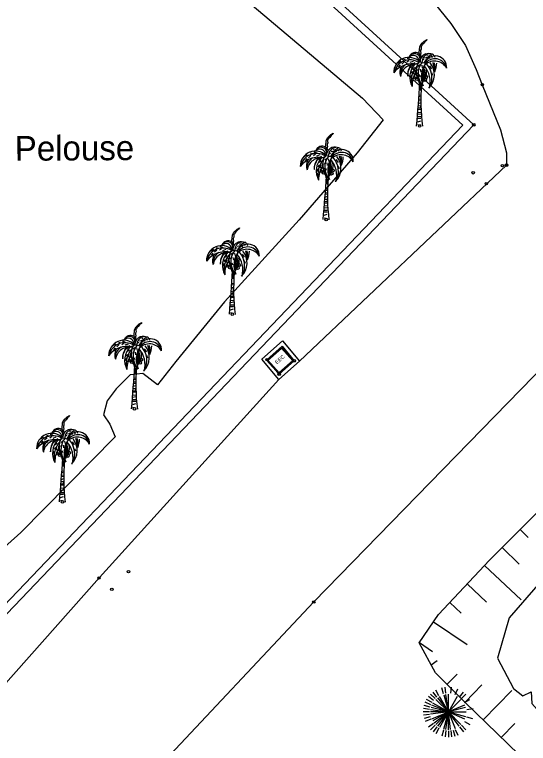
# Model space of a CAD drawing. Extents: x 344013 to 344423, y 298505 to 298795.
# Drawn here: x 344132.25 to 344152.54, y 298641.08 to 298669.85 of the extents above; entities that cross this region are included whole.
import ezdxf

# ---------------------------------------------------------------- set-up
doc = ezdxf.new("R2010")
doc.units = 0
for name, color, linetype in [('Default', 7, 'Continuous'), ('PS_BOLT', 7, 'Continuous'), ('PS_CONST', 7, 'Continuous'), ('RES_ELECTRICITE', 7, 'Continuous'), ('TOPO_POINT', 7, 'Continuous'), ('TOPO_TALUS-TERRAIN NATUREL', 7, 'Continuous'), ('VOIRIE_BORDURE', 7, 'Continuous'), ('VOIRIE_ESPACE VERT', 7, 'Continuous')]:
    doc.layers.add(name, color=color, linetype=linetype)

# ---------------------------------------------------------------- blocks, each defined once
blk = doc.blocks.new('RES_ELECTRICITE')
at = {"layer": 'RES_ELECTRICITE'}
for points in [[(0, 0), (0, 1), (1, 1), (1, 0)], [(0.05, 0.05), (0.05, 0.95), (0.95, 0.95), (0.95, 0.05)]]:
    blk.add_lwpolyline(points, close=True, dxfattribs=at)
blk.add_text('EEC', height=0.2, dxfattribs=at).set_placement((0.237, 0.46))
blk = doc.blocks.new('POINT_DISPLAY')
at = {"layer": 'Default'}
blk.add_circle((0, 0), 0.05, dxfattribs=at)
blk = doc.blocks.new('COCO')
at = {"layer": 'Default'}
for p, q in [((0.058, 1.14), (-0.03, 1.162)), ((-0.026, 1.226), (0.061, 1.212)), ((-0.046, 0.891), (0.052, 0.927)), ((0.054, 0.998), (-0.041, 0.985)), ((-0.037, 1.06), (0.056, 1.071)), ((0.047, 0.655), (-0.058, 0.642)), ((0.045, 0.292), (-0.07, 0.288)), ((-0.068, 0.371), (0.045, 0.374)), ((0.045, 0.47), (-0.065, 0.453)), ((-0.062, 0.537), (0.046, 0.552)), ((0.046, 0.033), (-0.076, 0.051)), ((-0.073, 0.17), (0.045, 0.209))]:
    blk.add_line(p, q, dxfattribs=at)
for points in [[(0.029, 2.551), (-0.016, 2.896), (0.002, 3.125), (0.059, 3.241), (0.173, 3.348), (0.189, 3.356), (0.282, 3.415), (0.266, 3.373), (0.2, 3.318), (0.143, 3.247), (0.093, 3.2), (0.081, 3.165), (0.057, 3.133), (0.057, 3.099), (0.06, 3.037), (0.039, 2.989), (0.039, 2.944), (0.049, 2.877), (0.037, 2.841), (0.013, 2.736)], [(-0.636, 2.639), (-0.541, 2.608)], [(-0.487, 2.68), (-0.386, 2.65)], [(0.013, 2.736), (0.036, 2.813), (0.046, 2.746)], [(0.133, 2.608), (0.185, 2.634)], [(0.196, 2.687), (0.323, 2.715)], [(0.283, 2.765), (0.331, 2.786)], [(-0.746, 2.559), (-0.864, 2.483)], [(-0.77, 2.413), (-0.836, 2.333)], [(-0.607, 2.534), (-0.704, 2.443)], [(-0.421, 2.58), (-0.503, 2.523)], [(-0.183, 2.493), (-0.348, 2.417), (-0.401, 2.307), (-0.448, 2.203), (-0.471, 2.086), (-0.474, 2.023), (-0.466, 1.973), (-0.455, 2.054), (-0.451, 2.146), (-0.387, 2.292), (-0.351, 2.354), (-0.284, 2.404), (-0.233, 2.445), (-0.012, 2.495)], [(-0.256, 2.553), (-0.385, 2.508)], [(-0.203, 2.314), (-0.274, 2.258)], [(0.015, 2.414), (-0.056, 2.352)], [(0.081, 2.404), (0.106, 2.299)], [(0.385, 2.37), (0.469, 2.254)], [(-0.276, 2.151), (-0.329, 2.086)], [(-0.23, 2.152), (-0.237, 2.043)], [(-0.161, 2.218), (-0.158, 2.122)], [(-0.059, 2.024), (-0.083, 1.998)], [(-0.04, 2.247), (-0.081, 2.179)], [(-0.025, 2.032), (0.002, 1.954)], [(0.022, 2.24), (0.043, 2.13)], [(0.473, 2.115), (0.509, 2.012)], [(-0.321, 1.997), (-0.364, 1.9)], [(-0.055, 0.716), (0.048, 0.717), (0.049, 0.787), (-0.051, 0.795)]]:
    blk.add_lwpolyline(points, dxfattribs=at)
for centre, radius in [((-0.144, 1.978), 0.0616), ((-0.187, 1.897), 0.0384), ((-0.124, 1.896), 0.0376), ((-0.11, 1.84), 0.0471), ((0.134, 1.862), 0.0549), ((0.208, 1.822), 0.0626), ((0.254, 1.938), 0.0628)]:
    blk.add_circle(centre, radius, dxfattribs=at)
for centre, radius, start, end in [((-0.16, 2.647), 0.255, 21.0861, 122.3475), ((-0.427, 2.113), 0.595, 43.6121, 181.4625), ((-0.38, 1.964), 0.648, 57.9192, 166.6201), ((-0.123, 2.59), 0.323, 122.3475, 158.7636), ((-0.199, 2.618), 0.238, 4.5218, 154.101), ((-0.252, 2.556), 0.231, 4.2441, 134.2103), ((0.376, 2.508), 0.372, 113.7681, 175.3309), ((0.376, 2.508), 0.372, 113.7681, 175.3309), ((0.418, 2.527), 0.326, 97.1248, 183.9512), ((1.025, 2.053), 0.958, 126.6858, 153.1664), ((0.618, 2.316), 0.451, 356.1627, 159.0009), ((0.609, 2.187), 0.468, 12.1077, 148.3146), ((0.344, 2.407), 0.451, 69.0817, 104.862), ((-0.157, 2.027), 0.74, 51.2475, 54.5217), ((-1.005, 1.577), 1.786, 37.5668, 40.5156), ((-0.254, 2.28), 0.869, 28.4725, 37.0965), ((0.493, 2.767), 0.0679, 35.3205, 126.6858), ((-0.054, 2.379), 0.738, 25.8194, 35.3205), ((-0.291, 1.543), 0.918, 76.7389, 142.8025), ((-0.3, 2.12), 0.482, 151.1331, 199.5942), ((-0.196, 1.874), 0.565, 78.514, 171.3504), ((-0.32, 2.055), 0.433, 119.0834, 188.7621), ((0.362, 1.922), 0.754, 136.7113, 208.8221), ((0.551, 1.79), 0.879, 137.733, 194.3716), ((0.62, 2.159), 0.753, 153.0868, 230.1124), ((0.659, 2.068), 0.718, 142.3554, 222.2794), ((-0.007, 2.465), 0.0563, 81.7475, 144.3035), ((-0.189, 1.21), 1.324, 71.3715, 81.7475), ((0.294, 2.595), 0.256, 198.6765, 199.7627), ((0.963, 1.939), 0.9, 143.9866, 203.4288), ((0.398, 2.098), 0.301, 136.4569, 162.0685), ((-0.404, 2.045), 0.619, 329.4666, 26.6793), ((0.59, 2.015), 0.548, 29.5654, 139.3517), ((-0.543, 1.744), 0.96, 344.8781, 41.1461), ((-0.341, 1.9), 0.828, 46.9767, 50.1231), ((-0.341, 1.9), 0.828, 334.0687, 41.194), ((-0.157, 2.027), 0.74, 315.1472, 39.0239), ((-1.704, 1.849), 2.327, 7.5978, 16.3666), ((-0.254, 2.28), 0.869, 350.8883, 14.7063), ((-0.482, 2.552), 1.161, 339.3597, 356.5925), ((0.649, 1.599), 0.949, 145.5146, 182.4528), ((0.544, 1.816), 0.474, 137.1953, 172.8987), ((0.308, 2.014), 0.226, 121.4297, 182.29), ((27.302, 0.106), 27.266, 175.4791, 176.5597), ((0.311, 2.152), 0.219, 141.856, 191.5175), ((0.372, 1.847), 0.277, 133.5956, 173.487), ((0.808, 1.542), 0.777, 142.2358, 156.28), ((0.242, 1.964), 0.147, 110.9727, 165.9756), ((0.404, 1.878), 0.354, 125.0585, 146.3893), ((0.357, 2.084), 0.244, 133.1184, 172.7534), ((-0.759, 1.958), 0.922, 344.8505, 15.8988), ((-0.289, 2.11), 0.564, 317.8279, 12.3386), ((-0.279, 1.637), 0.281, 2.1499, 36.6325), ((-85.428, 7.294), 85.622, 355.11326, 356.26352), ((-0.265, 1.505), 0.316, 339.9997, 25.7228), ((0.199, 1.66), 0.176, 166.9443, 185.5966)]:
    blk.add_arc(centre, radius, start, end, dxfattribs=at)
blk.add_ellipse((27.425, 0.272), major_axis=(-27.371, 0.966), ratio=0.529859, start_param=6.255729, end_param=6.369141, dxfattribs=at)
blk = doc.blocks.new('ARB2')
at = {"layer": 'Default'}
for p, q in [((-0.181, 0.716), (-0.244, 0.956)), ((-0.088, 0.736), (-0.119, 0.983)), ((0.106, 0.736), (0.144, 0.983)), ((0.287, 0.684), (0.388, 0.914)), ((-0.575, 0.453), (-0.775, 0.605)), ((-0.513, 0.525), (-0.688, 0.702)), ((-0.438, 0.589), (-0.588, 0.786)), ((-0.356, 0.642), (-0.481, 0.858)), ((0.456, 0.589), (0.612, 0.786)), ((0.531, 0.525), (0.706, 0.702)), ((-0.675, 0.286), (-0.9, 0.381)), ((-0.631, 0.373), (-0.844, 0.497)), ((0.65, 0.373), (0.862, 0.497)), ((-0.731, 0), (-0.981, 0)), ((-0.725, 0.1), (-0.969, 0.133)), ((-0.706, 0.195), (-0.944, 0.259)), ((0.744, 0.1), (0.987, 0.133)), ((-0.725, -0.1), (-0.969, -0.133)), ((-0.706, -0.195), (-0.944, -0.259)), ((-0.675, -0.287), (-0.9, -0.383)), ((0.725, -0.195), (0.963, -0.259)), ((-0.575, -0.455), (-0.775, -0.605)), ((-0.513, -0.527), (-0.688, -0.702)), ((0.531, -0.527), (0.706, -0.702)), ((0.65, -0.373), (0.862, -0.498)), ((-0.438, -0.591), (-0.588, -0.787)), ((-0.356, -0.644), (-0.481, -0.859)), ((-0.181, -0.717), (-0.244, -0.956)), ((-0.088, -0.737), (-0.119, -0.983)), ((0.013, -0.741), (0.013, -0.989)), ((0.106, -0.737), (0.144, -0.983)), ((0.2, -0.717), (0.263, -0.956)), ((0.287, -0.686), (0.388, -0.916)), ((0.456, -0.591), (0.612, -0.787))]:
    blk.add_line(p, q, dxfattribs=at)
for points in [[(-0.688, 0.091), (0.013, 0), (-0.338, 0.608)], [(-0.169, 0.677), (0.013, 0), (-0.6, 0.35)], [(0.013, 0.008), (0.013, 0), (-0.081, 0.695)], [(0.362, 0.608), (0.013, 0), (0.013, 0.702)], [(-0.487, 0.495), (0.013, 0), (-0.669, 0.181)], [(-0.419, 0.556), (0.013, 0), (-0.638, 0.269)], [(0.656, 0.269), (0.013, 0), (0.506, 0.495)], [(-0.487, -0.497), (0.013, 0), (-0.694, 0)], [(-0.638, -0.269), (0.013, 0), (-0.688, -0.092)], [(-0.169, -0.678), (0.013, 0), (-0.6, -0.352)], [(-0.544, -0.428), (0.013, 0), (-0.338, -0.608)], [(-0.081, -0.695), (0.013, 0), (-0.419, -0.558)], [(0.013, -0.702), (0.013, 0), (0, 0)], [(0.688, 0.181), (0.013, 0), (0.713, 0)], [(0.438, -0.558), (0.013, 0), (0.656, -0.269)], [(0.506, -0.497), (0.013, 0), (0.688, -0.181)], [(0.1, -0.695), (0.013, 0), (0.281, -0.648)], [(0.019, 0), (0.013, 0), (0.013, -0.009)]]:
    blk.add_lwpolyline(points, dxfattribs=at)

msp = doc.modelspace()

# ---------------------------------------------------------------- linework, layer by layer
at = {"layer": 'PS_BOLT'}
msp.add_lwpolyline([(344143.5, 298656.169), (344142.683, 298655.44), (344142.015, 298656.246), (344142.832, 298656.974)], close=True, dxfattribs=at)
at = {"layer": 'TOPO_TALUS-TERRAIN NATUREL'}
for p, q in [((344152.217, 298649.524), (344152.532, 298649.208)), ((344151.508, 298648.818), (344152.174, 298648.15)), ((344150.807, 298648.105), (344152.258, 298646.744)), ((344150.122, 298647.375), (344150.888, 298646.657)), ((344149.438, 298646.645), (344149.887, 298646.225)), ((344148.796, 298645.882), (344150.122, 298644.981)), ((344148.234, 298645.055), (344148.748, 298644.705)), ((344148.703, 298644.181), (344148.936, 298644.356)), ((344149.331, 298643.413), (344149.724, 298643.806)), ((344150.037, 298642.705), (344150.7, 298643.386)), ((344150.754, 298642.007), (344151.887, 298643.171)), ((344151.47, 298641.31), (344152.009, 298641.862))]:
    msp.add_line(p, q, dxfattribs=at)
for points in [[(344162.586, 298631.249), (344158.463, 298634.677), (344155.322, 298637.466), (344152.157, 298640.641), (344150.03, 298642.712), (344148.876, 298643.869), (344148.225, 298645.042), (344148.989, 298646.167), (344150.999, 298648.31), (344152.976, 298650.281), (344154.876, 298652.174), (344156.31, 298653.84), (344157.421, 298655.01), (344158.446, 298655.921), (344159.147, 298656.242), (344160.098, 298656.281)], [(344160.098, 298656.281), (344158.45, 298653.962), (344154.227, 298648.857), (344151.775, 298646.036), (344151.324, 298644.439), (344151.952, 298643.242), (344152.321, 298642.95), (344152.643, 298643.115), (344152.674, 298642.658), (344154.315, 298640.791), (344156.42, 298638.569), (344157.669, 298637.128), (344162.586, 298631.249)]]:
    msp.add_lwpolyline(points, dxfattribs=at)
at = {"layer": 'VOIRIE_BORDURE'}
for points in [[(344124.372, 298692.186), (344148.812, 298670.333), (344149.478, 298669.504), (344150.054, 298668.628), (344150.475, 298667.688), (344150.721, 298667.085), (344151.432, 298665.306), (344151.673, 298664.395), (344151.676, 298663.909), (344143.5, 298656.169), (344142.683, 298655.44), (344135.602, 298647.623), (344124.992, 298635.682)], [(344120.412, 298621.951), (344137.791, 298639.981), (344144.065, 298646.663), (344154.783, 298657.656), (344157.662, 298660.576), (344158.342, 298661.39), (344163.216, 298666.766), (344163.731, 298667.308), (344164.688, 298668.072), (344165.676, 298668.545), (344166.447, 298668.825), (344167.222, 298669.059), (344168.509, 298669.289), (344169.751, 298669.392), (344170.251, 298669.414), (344170.803, 298669.375), (344172.06, 298669.227), (344173.884, 298668.877), (344175.641, 298668.318), (344176.928, 298667.79), (344178.107, 298666.872), (344194.798, 298651.17), (344217.989, 298629.411), (344240.944, 298607.781)]]:
    msp.add_lwpolyline(points, dxfattribs=at)
msp.add_lwpolyline([(344143.292, 298656.184), (344142.699, 298655.656), (344142.223, 298656.23), (344142.816, 298656.759)], close=True, dxfattribs=at)
at = {"layer": 'VOIRIE_ESPACE VERT'}
msp.add_lwpolyline([(344129.915, 298683.811), (344149.954, 298665.484), (344120.649, 298634.816), (344119.758, 298634.843), (344094.693, 298657.614), (344119.626, 298684.533), (344119.467, 298684.803), (344094.267, 298657.595), (344119.638, 298634.546), (344120.774, 298634.512), (344150.383, 298665.499), (344130.117, 298684.033)], close=True, dxfattribs=at)
msp.add_lwpolyline([(344129.834, 298681.573), (344134.972, 298676.138), (344141.382, 298670.447), (344145.984, 298666.555), (344146.809, 298665.696), (344145.776, 298664.399), (344143.49, 298661.745), (344140.544, 298658.509), (344138.612, 298656.16), (344137.895, 298655.241), (344137.314, 298655.683), (344136.818, 298655.628), (344136.259, 298655.071), (344135.904, 298654.607), (344135.762, 298654.056), (344136.012, 298653.679), (344136.225, 298653.183), (344132.496, 298649.404), (344131.323, 298648.36)], dxfattribs=at)

# ---------------------------------------------------------------- block references
at = {"layer": 'RES_ELECTRICITE', "xscale": 0.794749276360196, "yscale": 0.7461633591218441, "rotation": 41.72266169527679}
msp.add_blockref('RES_ELECTRICITE', (344142.699, 298655.656), dxfattribs=at)
at = {"layer": 'TOPO_POINT'}
for p in [(344150.721, 298667.085), (344150.383, 298665.499), (344148.245, 298665.454), (344151.511, 298663.891), (344151.676, 298663.909), (344150.358, 298663.608), (344150.877, 298663.178), (344144.555, 298661.759), (344140.849, 298658.024), (344142.223, 298656.23), (344143.292, 298656.184), (344142.699, 298655.656), (344136.988, 298654.287), (344134.141, 298650.612), (344136.751, 298647.859), (344135.585, 298647.606), (344136.092, 298647.16), (344144.065, 298646.663), (344149.366, 298642.319)]:
    msp.add_blockref('POINT_DISPLAY', p, dxfattribs=at)
at = {"layer": 'VOIRIE_ESPACE VERT'}
for name, p in [('COCO', (344148.245, 298665.454)), ('COCO', (344144.555, 298661.759)), ('COCO', (344140.849, 298658.024)), ('COCO', (344136.988, 298654.287)), ('COCO', (344134.141, 298650.612)), ('ARB2', (344149.366, 298642.319))]:
    msp.add_blockref(name, p, dxfattribs=at)

# ---------------------------------------------------------------- texts
at = {"layer": 'PS_CONST'}
msp.add_text('Pelouse', height=0.9758, rotation=0.3665, dxfattribs=at).set_placement((344132.261, 298664.08))

doc.saveas('drawing.dxf')
